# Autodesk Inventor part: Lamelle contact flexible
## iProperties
Created: 2002-04
Part Number: Lamelle contact flexible
Material: Par défaut
Document SubType Name: Tôlerie
Designer: Flavien MARTY
Control State: 0
Master: False
Checked Out: False
Shininess: 20.0
Length Units: 11269
Angle Units: 11279
Time Units: 11290
Mass Units: 11283
Length Display Precision: 3
Angle Display Precision: 2
Compacted: True
Density: 0.0
Volumn: 0.0
Area: 0.0
PropertySet Name: Model Information
Author: Flavien MARTY
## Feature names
1. Pli2
2. Perçage1 [Hole]
3. Plaque1
4. Plaque2
5. Pli1
6. Plaque3
7. Pli3
8. Plaque4
9. Pli4
